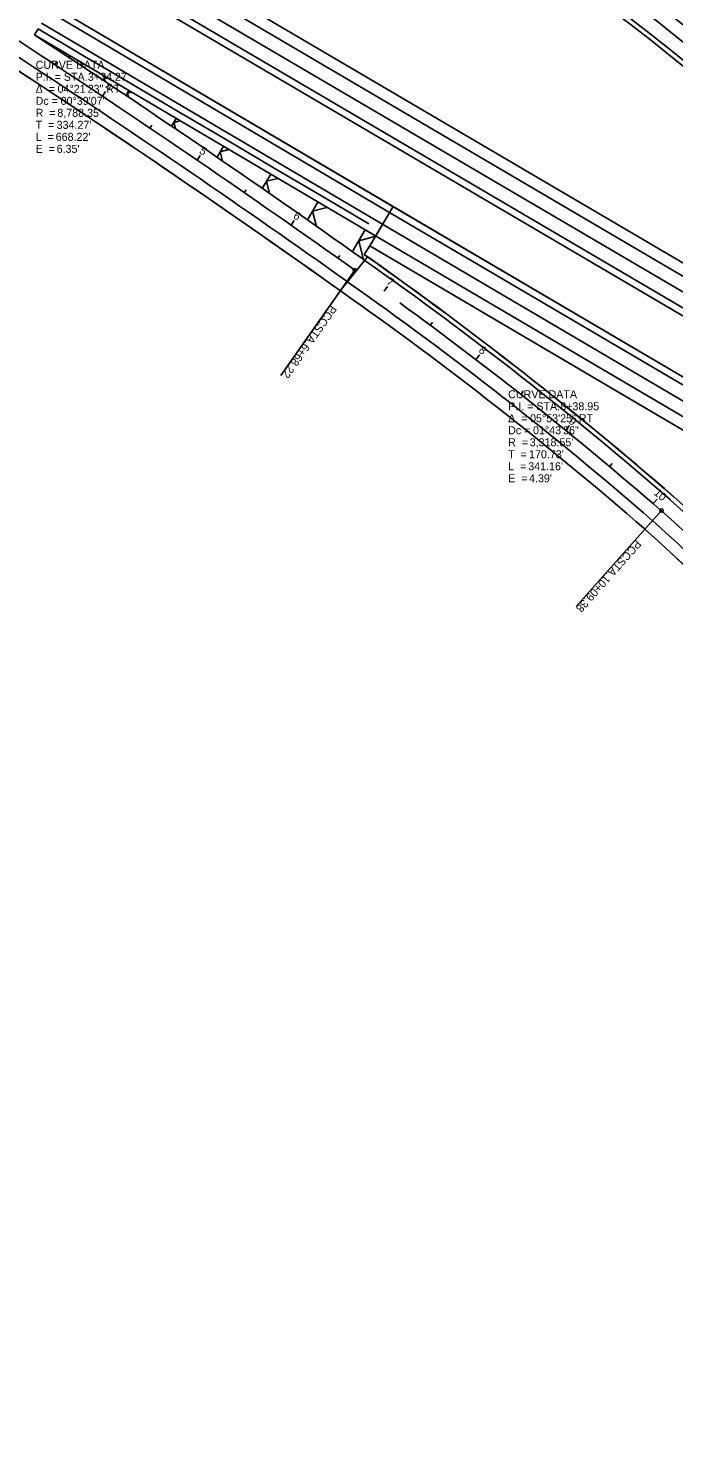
# Model space of a CAD drawing. Extents: x 76539 to 88870, y 518807 to 527554.
# Drawn here: x 86643 to 87208, y 521842 to 523086 of the extents above; entities that cross this region are included whole.
import ezdxf

# ---------------------------------------------------------------- set-up
doc = ezdxf.new("R2010")
doc.units = 0
for name, color, linetype in [('GE_P_Alignment_100_Cardinal_Points', 7, 'Continuous'), ('GE_P_Alignment_100_Curve_Data', 7, 'Continuous'), ('GE_P_Alignment_100_Stations', 7, 'Continuous'), ('PM_P_Channelizing_Line', 7, 'Continuous'), ('PM_P_Edge_Line', 7, 'Continuous'), ('PM_P_Lane_Line', 7, 'Continuous'), ('PV_P_Shoulder', 7, 'Continuous'), ('SC_Scratch1', 7, 'Continuous'), ('SC_Scratch2', 7, 'Continuous'), ('XS_P_Pavt_Surface', 7, 'Continuous')]:
    doc.layers.add(name, color=color, linetype=linetype)

msp = doc.modelspace()

# ---------------------------------------------------------------- linework, layer by layer
at = {"layer": 'GE_P_Alignment_100_Cardinal_Points'}
for p, q in [((86929, 522874.2), (86864.3, 522782.2)), ((87197.6, 522664.1), (87122.9, 522580))]:
    msp.add_line(p, q, dxfattribs=at)
for centre in [(86929, 522874.2), (87197.6, 522664.1)]:
    msp.add_circle(centre, 1.5, dxfattribs=at)
at = {"layer": 'GE_P_Alignment_100_Stations'}
for p, q in [((86666.4, 523054), (86668.1, 523056.5)), ((86708.1, 523026.4), (86710.9, 523030.5)), ((86749.6, 522998.5), (86751.3, 523001)), ((86791, 522970.4), (86793.8, 522974.6)), ((86832.2, 522942.1), (86833.9, 522944.6)), ((86873.2, 522913.6), (86876.1, 522917.7)), ((86914.1, 522884.8), (86915.9, 522887.2)), ((86954.9, 522855.8), (86957.8, 522859.9)), ((86995.3, 522826.4), (86997.1, 522828.8)), ((87035.3, 522796.4), (87038.3, 522800.3)), ((87074.8, 522765.7), (87076.6, 522768.1)), ((87113.8, 522734.5), (87117, 522738.4)), ((87152.4, 522702.7), (87154.3, 522705)), ((87190.5, 522670.3), (87193.7, 522674))]:
    msp.add_line(p, q, dxfattribs=at)
at = {"layer": 'PM_P_Channelizing_Line'}
msp.add_line((86648.6, 523080), (86950.2, 522902.4), dxfattribs=at)
for centre, radius, start, end in [((81834.3, 515713.3), 8788.4, 54.56975, 58.9262), ((81834.3, 515713.3), 8800.4, 54.56998, 56.83444), ((85021.2, 520158.9), 3330.6, 54.8622, 54.907)]:
    msp.add_arc(centre, radius, start, end, dxfattribs=at)
at = {"layer": 'PM_P_Edge_Line'}
for p, q in [((86028.6, 523566.6), (87281.2, 522830.8)), ((86016.5, 523545.9), (87269.1, 522810.1)), ((86660.8, 523100.7), (86962.3, 522923.1)), ((86962.3, 522923), (87239.7, 522760.1)), ((86950.2, 522902.4), (87227.5, 522739.4))]:
    msp.add_line(p, q, dxfattribs=at)
for centre, radius, start, end in [((86313.5, 521961.5), 1444.4, 9.2373, 64.1087), ((86313.5, 521961.5), 1444.4, 9.2373, 64.1087), ((86313.5, 521961.5), 1420.4, 9.25, 64.1087), ((81834.3, 515713.3), 8776.4, 54.56975, 58.9262), ((85021.2, 520158.9), 3330.6, 49.0174, 54.8622), ((85021.2, 520158.9), 3306.6, 49.0174, 54.9076), ((86249.5, 521595.5), 1440.6, 9.8352, 48.4209), ((86249.5, 521595.5), 1416.6, 9.9109, 48.4209)]:
    msp.add_arc(centre, radius, start, end, dxfattribs=at)
at = {"layer": 'PM_P_Lane_Line'}
for p, q in [((86022.6, 523556.3), (87275.1, 522820.5)), ((86654.7, 523090.4), (86956.2, 522912.7)), ((86956.3, 522912.7), (87233.6, 522749.8))]:
    msp.add_line(p, q, dxfattribs=at)
for centre, radius, start, end in [((86313.5, 521961.5), 1432.7, 9.2373, 64.1087), ((85021.2, 520158.9), 3318.2, 49.0174, 54.0656), ((86249.5, 521595.5), 1428.3, 9.8739, 48.4209)]:
    msp.add_arc(centre, radius, start, end, dxfattribs=at)
at = {"layer": 'PV_P_Shoulder'}
for p, q in [((86033.7, 523575.2), (87286.3, 522839.4)), ((86013.5, 523540.7), (87266, 522804.9)), ((86663.8, 523105.9), (86965.4, 522928.2)), ((86965.4, 522928.2), (87242.7, 522765.3)), ((86937.3, 522887.9), (86942.2, 522895.4)), ((86945.1, 522893.7), (86942.2, 522895.4)), ((86945.1, 522893.7), (87222.5, 522730.8)), ((86940.3, 522885.8), (86937.3, 522887.9))]:
    msp.add_line(p, q, dxfattribs=at)
for centre, radius, start, end in [((86313.5, 521961.5), 1454.4, 32.4027, 64.1087), ((86313.5, 521961.5), 1416.4, 39, 64.1087), ((81834.3, 515713.3), 8766.4, 54.56975, 58.9262), ((85021.2, 520158.9), 3334.6, 49.0174, 54.8622), ((85021.2, 520158.9), 3296.6, 49.0174, 54.9076), ((86249.5, 521595.5), 1406.6, 9.943, 48.4209)]:
    msp.add_arc(centre, radius, start, end, dxfattribs=at)
at = {"layer": 'SC_Scratch1'}
for p, q in [((86648.6, 523080), (86651.7, 523085.4)), ((86651.7, 523085.4), (86662.1, 523079.3)), ((86662.1, 523079.3), (86672.4, 523073.2)), ((86672.4, 523073.2), (86682.8, 523067.1)), ((86682.8, 523067.1), (86693.1, 523061)), ((86693.1, 523061), (86713.8, 523048.8)), ((86713.8, 523048.8), (86734.5, 523036.6)), ((86734.5, 523036.6), (86775.8, 523012.3)), ((86775.8, 523012.3), (86775.8, 523012.3)), ((86775.8, 523012.3), (86817.2, 522987.9)), ((86817.2, 522987.9), (86817.2, 522987.9)), ((86817.2, 522987.9), (86858.5, 522963.5)), ((86858.5, 522963.5), (86858.5, 522963.5)), ((86858.5, 522963.5), (86858.5, 522963.5)), ((86858.5, 522963.5), (86899.9, 522939.2)), ((86899.9, 522939.2), (86899.9, 522939.2)), ((86899.9, 522939.2), (86941.2, 522914.8)), ((86941.2, 522914.8), (86941.2, 522914.8))]:
    msp.add_line(p, q, dxfattribs=at)
at = {"layer": 'SC_Scratch2'}
for p, q in [((86658.9, 523073.9), (86658.6, 523073.4)), ((86658.8, 523073.7), (86659.2, 523073.8)), ((86658.8, 523073.7), (86658.9, 523073.3)), ((86669.3, 523067.8), (86668.7, 523066.8)), ((86669, 523067.3), (86669.8, 523067.5)), ((86669, 523067.3), (86669.2, 523066.5)), ((86679.6, 523061.7), (86678.7, 523060.2)), ((86679.2, 523061), (86680.4, 523061.3)), ((86679.2, 523061), (86679.5, 523059.7)), ((86690, 523055.7), (86688.7, 523053.6)), ((86689.4, 523054.6), (86691, 523055.1)), ((86689.4, 523054.6), (86689.8, 523052.9)), ((86710.6, 523043.5), (86708.8, 523040.3)), ((86709.7, 523041.9), (86712.2, 523042.5)), ((86709.7, 523041.9), (86710.4, 523039.3)), ((86731.3, 523031.3), (86728.8, 523027)), ((86730, 523029.1), (86733.5, 523030)), ((86730, 523029.1), (86733.5, 523030)), ((86730, 523029.1), (86731, 523025.5)), ((86730, 523029.1), (86731, 523025.5)), ((86772.7, 523006.9), (86768.7, 523000.1)), ((86770.7, 523003.5), (86776.1, 523004.9)), ((86770.7, 523003.5), (86772.2, 522997.8)), ((86814, 522982.6), (86808.4, 522973.1)), ((86811.2, 522977.8), (86818.8, 522979.8)), ((86811.2, 522977.8), (86813.3, 522969.7)), ((86855.4, 522958.2), (86848, 522945.7)), ((86855.4, 522958.2), (86848, 522945.7)), ((86851.7, 522952), (86861.6, 522954.5)), ((86851.7, 522952), (86854.5, 522941.3)), ((86896.7, 522933.8), (86887.5, 522918.2)), ((86892.1, 522926), (86904.6, 522929.2)), ((86892.1, 522926), (86895.6, 522912.5)), ((86938.1, 522909.5), (86926.9, 522890.5)), ((86932.5, 522900), (86947.6, 522903.9)), ((86932.5, 522900), (86936.8, 522883.4))]:
    msp.add_line(p, q, dxfattribs=at)
at = {"layer": 'XS_P_Pavt_Surface'}
for p, q in [((87286.3, 522839.4), (86033.7, 523575.2)), ((86013.5, 523540.7), (87266, 522804.9)), ((86962.6, 522929.9), (86663.8, 523105.9)), ((86942.2, 522895.4), (86962.6, 522929.9)), ((86942.2, 522895.4), (86962.6, 522929.9)), ((86962.6, 522929.9), (87239.8, 522767)), ((86937.3, 522887.9), (86942.2, 522895.4)), ((87219.5, 522732.5), (86942.2, 522895.4)), ((86916.3, 522856.2), (86940.3, 522885.8)), ((86940.3, 522885.8), (86937.3, 522887.9))]:
    msp.add_line(p, q, dxfattribs=at)
for centre, radius, start, end in [((86313.5, 521961.5), 1454.4, 32.4027, 64.1087), ((86313.5, 521961.5), 1416.4, 39, 64.1087), ((81834.3, 515713.3), 8766.4, 54.5689, 58.92582), ((85020.1, 520157.6), 3336.2, 49.0158, 54.8606), ((85021.2, 520158.9), 3296.6, 49.0174, 54.9076), ((86249.5, 521595.5), 1444.6, 9.8228, 48.4209), ((86249.8, 521595.6), 1406.3, 9.9383, 48.4162)]:
    msp.add_arc(centre, radius, start, end, dxfattribs=at)

# ---------------------------------------------------------------- texts
at = {"layer": 'GE_P_Alignment_100_Cardinal_Points'}
for s, rotation, p in [('PCC', 234.9076, (86908, 522844.2)), (' STA. ', 234.9076, (86898.1, 522830.1)), ('6+68.22', 234.9076, (86884.5, 522810.8)), ('PCC', 228.4209, (87175.3, 522638.8)), (' STA. ', 228.4209, (87163.8, 522625.9)), ('10+09.38', 228.4209, (87148.2, 522608.3))]:
    msp.add_text(s, height=7, rotation=rotation, dxfattribs=at).set_placement(p)
at = {"layer": 'GE_P_Alignment_100_Curve_Data'}
for s, p in [('CURVE DATA', (86649.6, 523050.4)), ('P.I. = STA. ', (86649.6, 523039.9)), ('3+34.27', (86695.3, 523039.9)), ('Δ  = ', (86649.6, 523029.4)), ('Dc = ', (86649.6, 523018.9)), ('04°21\'23" RT', (86668.8, 523029.4)), ('00°39\'07"', (86671.5, 523018.9)), ('R  = ', (86649.6, 523008.4)), ("8,788.35'", (86668.6, 523008.4)), ('T  = ', (86649.6, 522997.9)), ("334.27'", (86668, 522997.9)), ('L  = ', (86649.6, 522987.4)), ("668.22'", (86667.2, 522987.4)), ('E  = ', (86649.6, 522976.9)), ("6.35'", (86668, 522976.9)), ('CURVE DATA', (87063.3, 522762.2)), ('P.I. = STA. ', (87063.3, 522751.7)), ('8+38.95', (87108.9, 522751.7)), ('Δ  = ', (87063.3, 522741.2)), ('05°53\'25" RT', (87082.5, 522741.2)), ('Dc = ', (87063.3, 522730.7)), ('R  = ', (87063.3, 522720.2)), ("3,318.55'", (87082.2, 522720.2)), ('01°43\'36"', (87085.1, 522730.7)), ('T  = ', (87063.3, 522709.7)), ("170.73'", (87081.6, 522709.7)), ('L  = ', (87063.3, 522699.2)), ("341.16'", (87080.9, 522699.2)), ('E  = ', (87063.3, 522688.7)), ("4.39'", (87081.6, 522688.7))]:
    msp.add_text(s, height=7, dxfattribs=at).set_placement(p)
at = {"layer": 'GE_P_Alignment_100_Stations'}
for s, rotation, p in [('4', 326.3184, (86709.4, 523033)), ('5', 325.6664, (86792.3, 522977.1)), ('6', 325.0145, (86874.5, 522920.3)), ('7', 324.3588, (86956.1, 522862.6)), ('8', 322.6323, (87036.9, 522803)), ('9', 320.9058, (87115.7, 522741)), ('10', 319.1792, (87190.3, 522678.6))]:
    msp.add_text(s, height=7, rotation=rotation, dxfattribs=at).set_placement(p)

doc.saveas('drawing.dxf')
